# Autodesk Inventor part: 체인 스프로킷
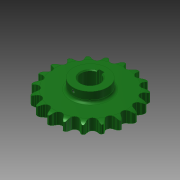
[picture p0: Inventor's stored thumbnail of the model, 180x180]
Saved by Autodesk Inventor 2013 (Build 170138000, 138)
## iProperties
Created: 2013-01
Part Number: 체인 스프로킷
Material: 강철, 연강
Document SubType Name: Modeling
Designer: mdu
Density: 1 g/cm^3
CustomPartVersion: 1
Author: mdu
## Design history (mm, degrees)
sketch "이론적 톱니 프로파일"
  geometry: L1 (0, 0)-(0, 45.567); L2 (0, 0)-(14.795, 43.098); L3 (0, 45.567)-(14.795, 43.098); L4 (0, 45.567)-(5.661, 50.015); L5 (5.661, 50.015)-(-5.141, 45.406); L6 (-12.428, 43.493)-(-5.573, 46.417); L7 (-5.141, 45.406)-(-5.573, 46.417); L8 (5.573, 46.417)-(5.141, 45.406); L9 (0, 0)-(8.138, 48.771); A1 r 45.567 centre (0, 0) between (0, 45.567) and (14.795, 43.098); A2 r 49.445 centre (0, 0) between (7.302, 48.903) and (-7.302, 48.903); A3 r 4.545 centre (0, 45.567) between (-3.574, 42.758) and (3.574, 42.758); A4 r 7.453 centre (12.428, 43.493) between (7.302, 48.903) and (5.573, 46.417); A5 r 7.453 centre (-12.428, 43.493) between (-5.573, 46.417) and (-7.302, 48.903); A6 r 11.745 centre (5.661, 50.015) between (-5.141, 45.406) and (-3.574, 42.758); A7 r 11.745 centre (-5.661, 50.015) between (3.574, 42.758) and (5.141, 45.406); 2 further points
  constraints: 18 end point, 15 point on circle, 7 centre point, 3 coincident, 3 point on line, 3 symmetric about line, 3 tangent, 1 equal radius, 1 midpoint, 1 parallel, 1 vertical, 1 other
  dimensions: "d0" = 91.13301 diameter of A1 (computed from da_p, da_z); "d2" = 18.9474 deg angle of L2 L1 (computed from da_z); "d3" = 4.545 radius of A3 (= 0.5 x da_Dr + da_SC); "d10" = 128.158 deg angle of L4 L1 (computed from da_z); "d11" = 15.0526 deg angle of L5 L4 (computed from da_z); "d12" = 7.2 distance of L3.start L4.end (= 0.8 x da_Dr); "d13" = 11.745 distance of L4.end L5.end (= 1.3 x da_Dr + da_SC); "d14" = 12.6 distance of A4.centre L1.end (= 1.4 x da_Dr); "d23" = 4.5 distance from line of L9.end L3 (= da_Ha)
sketch "톱니 프로파일"
  geometry: L1 (0, 0)-(0, 45.567); L2 (0, 45.567)-(4.203, 43.837); L3 (0, 45.567)-(-4.203, 43.837); A1 r 4.545 centre (0, 45.567) between (-4.203, 43.837) and (4.203, 43.837); A2 r 22.68 centre (25.176, 35.206) between (7.12, 48.93) and (4.203, 43.837); A3 r 22.68 centre (-25.176, 35.206) between (-4.203, 43.837) and (-7.12, 48.93); A4 r 49.445 centre (0, 0) between (-7.12, 48.93) and (7.12, 48.93) reference; 1 further point
  constraints: 9 point on circle, 6 end point, 3 centre point, 2 tangent, 1 coincident, 1 equal radius, 1 vertical, 1 other
  dimensions: "d44" = 135.263 deg angle of L3 L2 (= da_Alfa); "d45" = 22.68 radius of A2 (= da_Re); "d46" = 4.545 radius of A1 (= da_Ri)
sketch "단면 프로파일"
  geometry: L1 (49.445, 0)-(-49.445, 0) reference; L2 (33.265, 6.65)-(-33.265, 6.65); L3 (-33.265, 6.65)-(-33.265, -6.65); L4 (-33.265, -6.65)-(33.265, -6.65); L5 (33.265, -6.65)-(33.265, 6.65); L6 (33.265, 6.65)-(49.445, 6.65); L7 (49.445, 6.65)-(49.445, -6.65); L8 (49.445, -6.65)-(33.265, -6.65); L9 (33.265, -6.65)-(33.265, 6.65); L10 (42.183, 6.65)-(0, 6.65); L11 (0, 6.65)-(0, -6.65); L12 (0, -6.65)-(42.183, -6.65); L13 (0, 6.65)-(0, -6.65); L14 (49.445, 4.775)-(49.445, -4.775); A1 r 15 centre (42.183, -8.35) between (49.445, 4.775) and (42.183, 6.65); A2 r 15 centre (42.183, 8.35) between (42.183, -6.65) and (49.445, -4.775); 2 further points
  constraints: 26 end point, 7 midpoint, 5 perpendicular, 4 parallel, 4 point on circle, 3 point on line, 3 symmetric about line, 2 centre point, 2 horizontal, 2 tangent, 1 collinear, 1 other
  dimensions: "d30" = 13.3 distance between parallel lines of L8 L6 (= da_Bf); "d31" = 66.53007 distance between parallel lines of L3 L5 (= da_Ds); "d32" = 13.3 distance between parallel lines of L4 L2 (= da_Bs); "d33" = 1.875 distance from line of L14.start L6 (= da_Ba); "d34" = 15 radius of A1 (= da_Rx); "d43" = 6.65 distance between parallel lines of L4 L1 (computed from da_k, da_pt, da_Bs)
revolve "슈라우드" stored, may be unused: angle "d36" = 90 deg
revolve "스트랜드" stored, may be unused: angle "d37" = 90 deg
extrude "이론적 톱니" cut sketch "이론적 톱니 프로파일" stored distance "d18" = 10; taper "d19" = 0 deg; dims "d49" = 0, "form_type" = 0 [user parameter]
extrude "톱니" cut sketch "톱니 프로파일" stored distance "d47" = 10; taper "d48" = 0 deg; dims "d50" = 10, "form_type" = 0 [user parameter]
node "타이밍 평면"
node "작업 평면3"
sketch "스케치5"
  geometry: C1 r 20 at (0, -45.567); 1 further point
  constraints: 1 centre point, 1 coincident
  dimensions: "d52" = 40 diameter of C1
extrude "돌출4" join sketch "스케치5" stored distance "d53" = 10; taper "d54" = 0 deg
sketch "스케치6"
  geometry: L1 (3, 10.583)-(3, 13.8); L2 (3, 13.8)-(-3, 13.8); L3 (-3, 13.8)-(-3, 10.583); A1 r 11 centre (0, 0) between (3, 10.583) and (-3, 10.583); 1 further point
  constraints: 6 end point, 2 parallel, 2 point on circle, 1 centre point, 1 coincident, 1 perpendicular, 1 vertical
  dimensions: "d55" = 22 diameter of A1; "d56" = 24.8 dimension on A1 L2 (computed from d55); "d57" = 6 distance of L1.end L2.end
extrude "돌출5" cut sketch "스케치6" stored distance "d58" = 10; taper "d59" = 0 deg
fillet "모깎기2" dims "d60" = 3
chamfer "모따기1" distance "d61" = 1; stored, may be unused: second distance "d62" = 2, angle "d63" = 45 deg
node "작업 평면4"
sketch "스케치7"
  geometry: L1 (20, 11.7)-(-20, 11.7) reference; 2 further points
  constraints: 1 vertical alignment
  dimensions: "d64" = 4 distance from line of L1 point (0, 7.7)
hole "구멍1" sketch "스케치7" at (0, 7.7) diameter "d65" = 3.242; stored, may be unused: countersink angle "d69" = 90 deg, drill point angle "d71" = 118 deg; dims "d66" = 6, "d67" = 4, "d68" = 2, "d70" = 8
body "Solid1"
pattern_linear "스트랜드 패턴" dims "d40" = 24 (= da_pt)
pattern_circular "톱니 패턴" dims angle "d21" = 360 deg
other parameters: "da_p" = 15 [user parameter; used in 1 equation term], "da_Dr" = 9 [user parameter; used in 4 equation terms], "da_SC" = 0.045 [user parameter; used in 2 equation terms], "da_Ha" = 4.5 [user parameter; used in 1 equation term], "da_pt" = 24 [user parameter; used in 2 equation terms], "da_Bf" = 13.3 [user parameter; used in 1 equation term], "d28" = 0, "d29" = 0, "da_Ba" = 1.875 [user parameter; used in 1 equation term], "da_Rx" = 15 [user parameter; used in 1 equation term], "da_Ra" = 0.6 [user parameter], "da_Bs" = 13.3 [user parameter; used in 2 equation terms], "da_Ds" = 66.53007 [user parameter; used in 1 equation term], "d42" = 0, "da_Re" = 22.68 [user parameter; used in 1 equation term], "da_Ri" = 4.545 [user parameter; used in 1 equation term], "da_Alfa" = 135.263 deg [user parameter; used in 1 equation term], "d51" = -25
